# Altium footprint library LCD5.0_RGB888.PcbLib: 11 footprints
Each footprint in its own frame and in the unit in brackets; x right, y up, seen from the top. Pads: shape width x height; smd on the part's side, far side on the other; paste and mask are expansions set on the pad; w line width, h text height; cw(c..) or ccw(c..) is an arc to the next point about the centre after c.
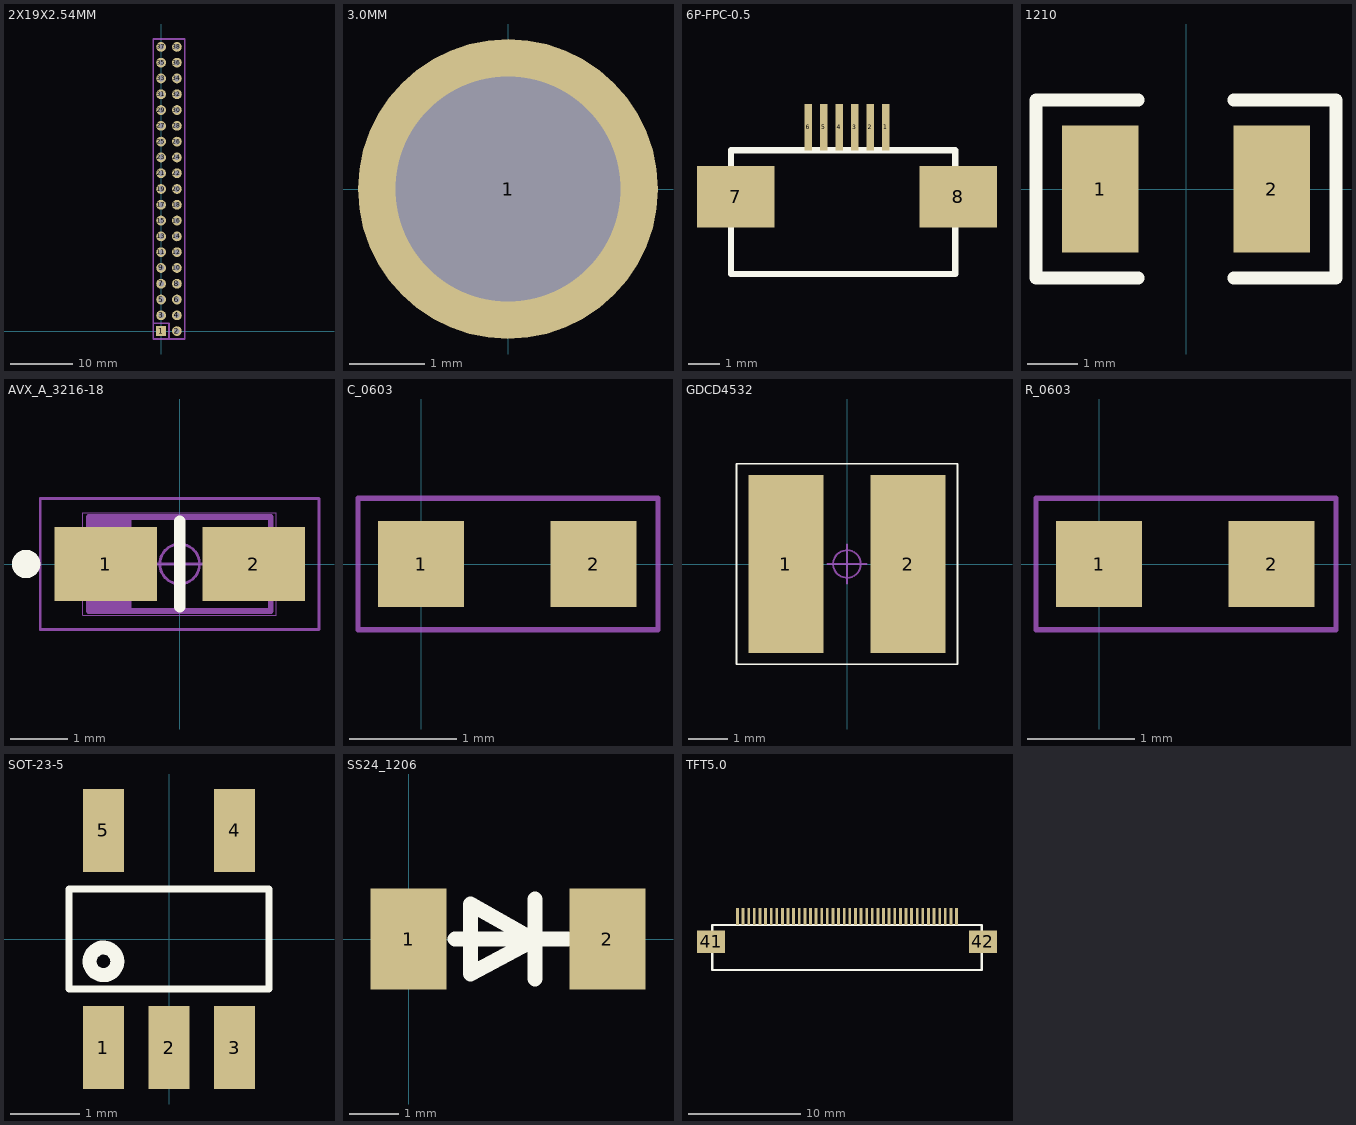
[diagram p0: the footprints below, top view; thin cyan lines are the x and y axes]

## 2X19X2.54MM [mil]
pads (38):
  rrect0% 62x62 all layers, no hole: 1(0,0)
  round 62 hole 35.43: 2(100,0) 3(0,100) 4(100,100) 5(0,200) 6(100,200) 7(0,300) 8(100,300) 9(0,400) 10(100,400) 11(0,500) 12(100,500) 13(0,600) 14(100,600) 15(0,700) 16(100,700) 17(0,800) 18(100,800) 19(0,900) 20(100,900) 21(0,1000) 22(100,1000) 23(0,1100) 24(100,1100) 25(0,1200) 26(100,1200) 27(0,1300) 28(100,1300) 29(0,1400) 30(100,1400) 31(0,1500) 32(100,1500) 33(0,1600) 34(100,1600) 35(0,1700) 36(100,1700) 37(0,1800) 38(100,1800)
Mechanical 1:
  lines w12: -50,50 50,50 50,-50 ; -50,-50 -50,1850 150,1850 150,-50 -50,-50

## 3.0MM [mm]
pads (1):
  round 4 hole 3: 1(0,0)

## 6P-FPC-0.5 [mm]
pads (8):
  rect 0.25x1.5 smd: 1(46,43.45) 2(45.5,43.45) 3(45,43.45) 4(44.5,43.45) 5(44,43.45) 6(43.5,43.45)
  rect 2.5x2 smd: 7(41.15,41.2) 8(48.35,41.2)
Top Overlay:
  lines w0.2: 41,38.7 41,42.7 48.25,42.7 48.25,38.7 41,38.7

## 1210 [mil]
pads (2):
  rect 60x100 smd: 1(-67.5,0) 2(67.5,0)
Top Overlay:
  lines w10: -37.5,-70 -118,-70 -118,70 -37.5,70 ; 37.5,-70 118,-70 118,70 37.5,70

## AVX_A_3216-18 [mm]
height 1.6
pads (2):
  rect 1.8x1.3 smd: 1(-1.3,0) 2(1.3,0)
Top Overlay:
  circle w0.25: c-2.7,0 r0.125
  lines w0.2: 0,-0.75 0,0.75
Mechanical 1:
  lines w0.1: -1.5,-0.825 -1.5,0.825 ; -1.4,-0.825 -1.4,0.825 ; -1.3,-0.825 -1.3,0.825 ; -1.2,-0.825 -1.2,0.825 ; -1.1,-0.825 -1.1,0.825 ; -1,-0.825 -1,0.825 ; -0.9,-0.825 -0.9,0.825 ; -1.6,-0.825 -1.6,0.825 1.6,0.825 1.6,-0.825 -1.6,-0.825
Mechanical 16:
  circle w0.05: c0,0 r0.35
  lines w0.001: -1.7,-0.9 -1.7,0.9 1.7,0.9 1.7,-0.9 -1.7,-0.9
  lines w0.05: -0.5,0 0.5,0 ; 0,-0.5 0,0.5 ; -2.45,-1.15 -2.45,1.15 2.45,1.15 2.45,-1.15 -2.45,-1.15

## C_0603 [mm]
pads (2):
  rect 0.8x0.8 smd: 1(0,0) 2(1.6,0)
Mechanical 1:
  lines w0.051: -0.584,-0.61 -0.584,0.61 2.197,0.61 2.197,-0.61 -0.584,-0.61

## GDCD4532 [mm]
height 5.3
pads (2):
  rect 1.9x4.5 smd: 1(-1.55,0) 2(1.55,0)
Top Overlay:
  lines w0.05: -2.794,-2.54 2.794,-2.54 2.794,2.54 -2.794,2.54 -2.794,-2.54
Mechanical 16:
  circle w0.05: c0,0 r0.35
  lines w0.05: -0.5,0 0.5,0 ; 0,-0.5 0,0.5

## R_0603 [mm]
pads (2):
  rect 0.8x0.8 smd: 1(0,0) 2(1.6,0)
Mechanical 1:
  lines w0.051: -0.584,-0.61 -0.584,0.61 2.197,0.61 2.197,-0.61 -0.584,-0.61

## SOT-23-5 [mm]
pads (5):
  rect 0.6x1.2 smd: 1(-0.95,-1.575) 2(0,-1.575) 3(0.95,-1.575) 4(0.95,1.575) 5(-0.95,1.575)
Top Overlay:
  circle w0.203: c-0.95,-0.325 r0.2
  lines w0.102: -1.45,-0.725 -1.45,0.475 -1.45,0.725 1.45,0.725 1.45,0.475 1.45,-0.725 -1.45,-0.725

## SS24_1206 [mil]
pads (2):
  rect 60x80 smd: 1(0,0) 2(157.48,0)
Top Overlay:
  lines w12: 36.92,-0.13 125.98,-0.13 ; 100.17,-31.5 100.17,31.5 ; 49.17,-27.56 49.17,27.56 100.17,-1.13 100.17,-0.13 49.17,-27.56

## TFT5.0 [mm]
pads (42):
  rect 0.25x1.5 smd: 1(46,43.45) 2(45.5,43.45) 3(45,43.45) 4(44.5,43.45) 5(44,43.45) 6(43.5,43.45) 7(43,43.45) 8(42.5,43.45) 9(42,43.45) 10(41.5,43.45) 11(41,43.45) 12(40.5,43.45) 13(40,43.45) 14(39.5,43.45) 15(39,43.45) 16(38.5,43.45) 17(38,43.45) 18(37.5,43.45) 19(37,43.45) 20(36.5,43.45) 21(36,43.45) 22(35.5,43.45) 23(35,43.45) 24(34.5,43.45) 25(34,43.45) 26(33.5,43.45) 27(33,43.45) 28(32.5,43.45) 29(32,43.45) 30(31.5,43.45) 31(31,43.45) 32(30.5,43.45) 33(30,43.45) 34(29.5,43.45) 35(29,43.45) 36(28.5,43.45) 37(28,43.45) 38(27.5,43.45) 39(27,43.45) 40(26.5,43.45)
  rect 2.5x2 smd: 41(24.15,41.2) 42(48.35,41.2)
Top Overlay:
  lines w0.2: 24.25,38.7 24.25,42.7 48.25,42.7 48.25,38.7 24.25,38.7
